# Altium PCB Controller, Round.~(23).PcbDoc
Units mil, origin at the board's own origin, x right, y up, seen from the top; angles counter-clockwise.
Board outline 1800 x 1800 mil, 4 copper layers (Top Layer, Signal 1, Signal 2, Bottom Layer); 49 components, 56 nets, 216 pads, 8 vias.
Unrouted connection lines stored in the file: 90.
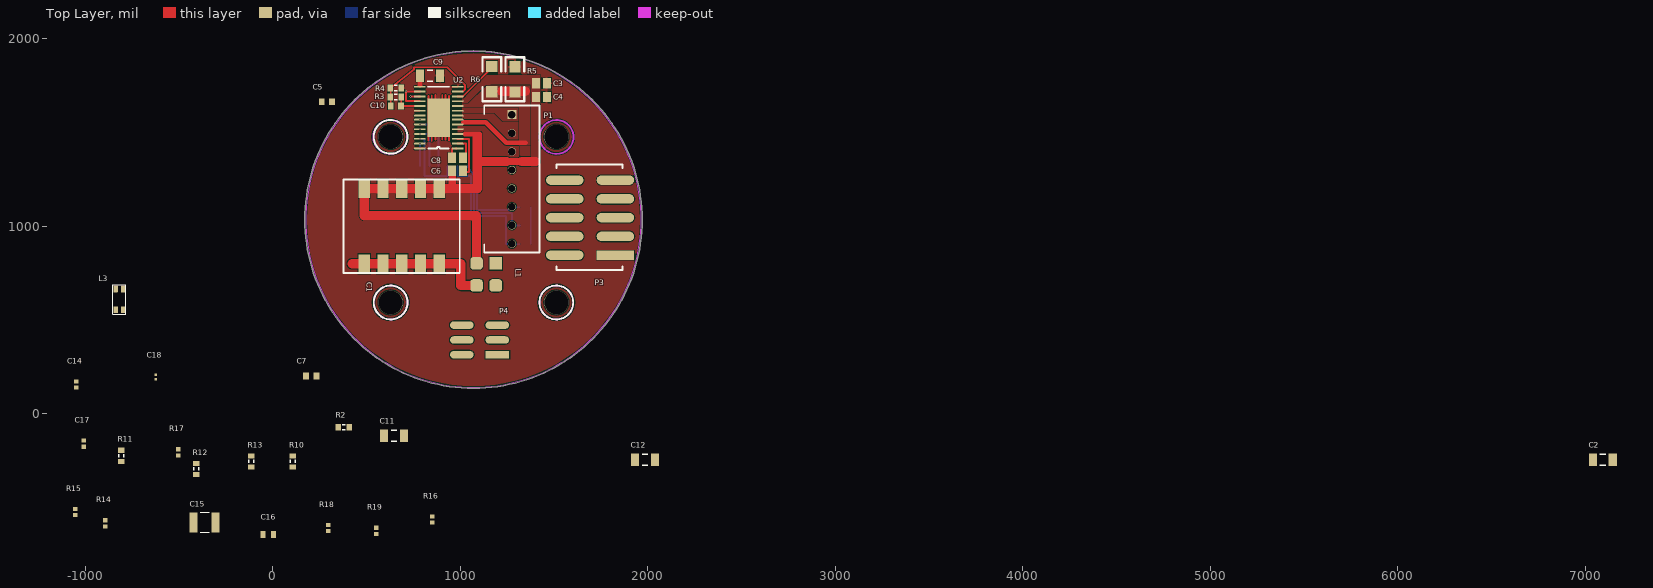
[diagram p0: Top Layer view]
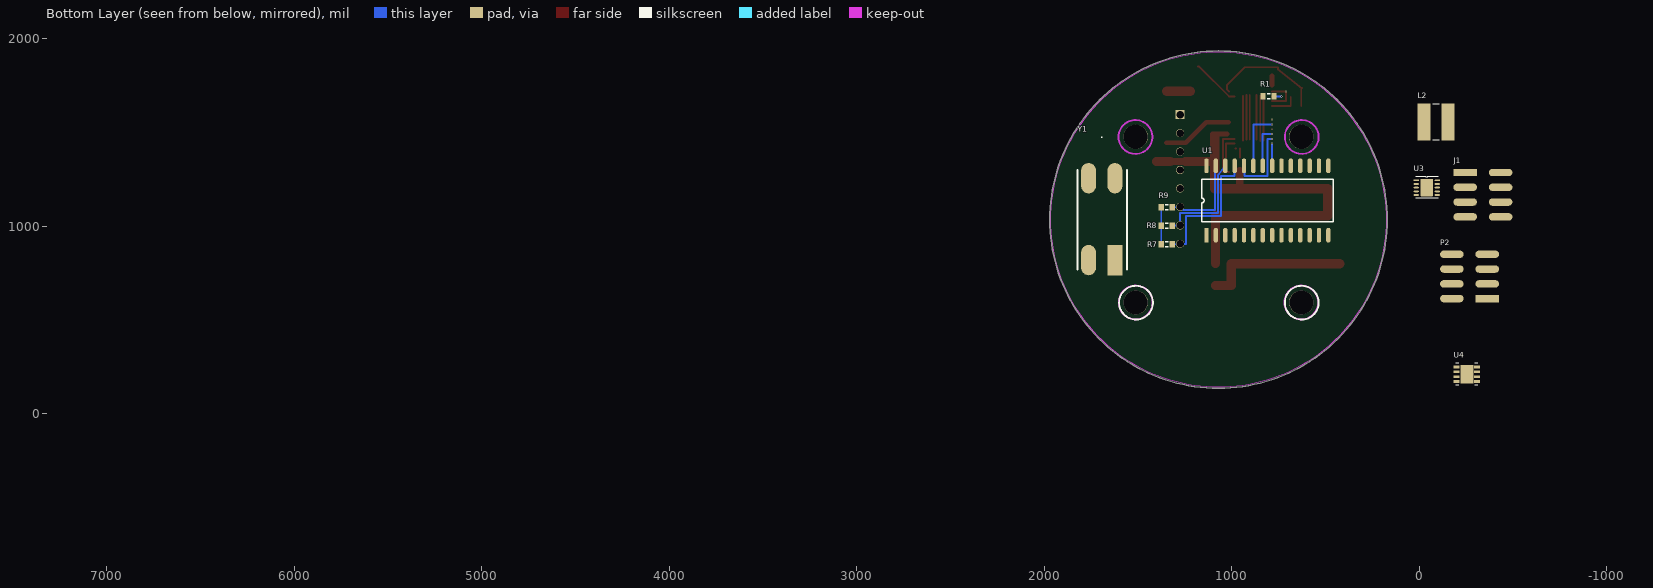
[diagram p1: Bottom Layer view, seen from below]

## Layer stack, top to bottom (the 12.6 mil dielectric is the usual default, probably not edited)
Top Layer: signal copper 1.4
Dielectric: core 12.6, FR-4, Dk 4.8
Signal 1: signal copper 1.4
Dielectric: prepreg 12.6, FR-4, Dk 4.8
Signal 2: signal copper 1.4
Dielectric: core 12.6, FR-4, Dk 4.8
Bottom Layer: signal copper 1.4

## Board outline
1070,135 cw(c1070,1035) 170,1035 cw(c1070,1035) 1070,1935 cw(c1070,1035) 1970,1035 cw(c1070,1035)

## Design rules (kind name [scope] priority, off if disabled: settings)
Clearance [All] p1: gap=5
HoleSize [All] p1: absolutevalues=TRUE maxlimit=130 minlimit=1 maxpercent=80.000 minpercent=20.000
PolygonConnect PolygonConnect_2 [WithinRoom('DontPour1') vs InNet('GND')] p1: connectstyle=NoConnect reliefconductorwidth=10 reliefentries=4 polygonreliefangle="90 Angle"
PolygonConnect PolygonConnect_1 [(InComponent('C1')) vs InNet('GND')] p2: connectstyle=NoConnect reliefconductorwidth=10 reliefentries=4 polygonreliefangle="90 Angle"
PolygonConnect [(InNet('NetP1_1') OR InNet('NetP1_2') OR InNet('NetP1_3') OR InNet('VM') OR InNet('VSENSE')) vs (InNet('NetP1_1') OR InNet('NetP1_2') OR InNet('NetP1_3') OR InNet('VM') OR InNet('VSENSE'))] p3: connectstyle=Direct reliefconductorwidth=10 reliefentries=4 polygonreliefangle="90 Angle"
RoomDefinition DontPour1 [InNet('GND') And OnLayer('TopLayer')] p1: confinementstyle=ConfineOut formatcopy=TRUE lockcomponents=FALSE outline 919.36,858.74 1037.37,858.74 1037.71,793.67 1037.71,732.35 1138.77,732.35 1138.77,624.69 920.46,624.69 920.46,640.36
RoomDefinition Controller [InComponentClass('Controller')] p2: confinementstyle=ConfineIn formatcopy=TRUE lockcomponents=FALSE outline -1190,-875 7190,-875 7190,2350 -1190,2350
RoutingVias [All] p1: holewidth=28 width=50 viastyle="Through Hole" minholewidth=6 minwidth=7.5 maxholewidth=28 maxwidth=50
SilkscreenOverComponentPads [All] p1: minsilkscreentomaskgap=10
SolderMaskExpansion [All] p1: expansion=4
Width [InNet('VM')] p1: maxlimit=100 minlimit=20 preferedwidth=40
26 further rules are at their usual default settings.

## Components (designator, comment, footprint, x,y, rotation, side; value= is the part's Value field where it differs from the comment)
C1 "Cap Pol1" CAPSTICK-CS4-5-SMD 486.68,1199.77 r0 top
C2 "Cap Semi" C1206 7095,-245 r0 top
C3 "Cap Semi" C0805 1432,1763 r180 top
C4 "Cap Semi" C0805 1432,1689 r180 top
C5 "Cap Semi" 1608[0603] 288,1664 r0 top
C6 "Cap Semi" C0805 985,1295 r180 top
C7 "Cap Semi" 1608[0603] 204,201 r0 top
C8 "Cap Semi" C0805 985,1365 r180 top
C9 "Cap Semi" C1206 838,1803 r180 top
C10 "Cap Semi" 1608[0603] 656,1641.38 r180 top
C11 "Cap Semi" C1206 646,-119 r0 top
C12 "Cap Semi" C1206 1985,-245 r0 top
C14 "C1005X7R1E103K" 0402 -1050,155 r90 top
C15 "C3225X7R2A225K230AB" 1210 -365,-580 r0 top
C16 "C1608X5R0J106M" 0603 -25,-645 r0 top
C17 "C0402C330J5GAC" 0402 -1010,-160 r90 top
C18 "GRM033R61A472KA01D" 0201 -625,195 r90 top
J1 "M80-8280842" M8082808DIL -435,1050 r0 bottom
L1 "DLW5BTM501SQ2" DLW5A_5B 1086.3,801.85 r0 top
L2 "LPS5030-823MLB" LPS5030 -90,1555 r180 bottom
L3 "SRF3216-222Y" SRF3216 -800,555 r180 top
P1 "MKS 1658-6-0-808" MKS_1658_A_KF 1275,1595 r270 top
P2 "M80-8280842" M8082808DIL -175,850 r180 bottom
P3 "N2510-6V0C-RB-WD" N2510_SMD 1826.98,845.64 r180 top
P4 "M80-8280642" M8082806DIL 1008,472 r0 top
R1 "Res3" J1-0603 803,1694 r180 bottom
R2 "Res3" J1-0603 378,-72 r0 top
R3 "Res3" J1-0603 655,1689 r0 top
R4 "Res3" J1-0603 655,1737 r180 top
R5 "Res3" 1206 1291,1851 r270 top
R6 "Res3" 1206 1168,1717 r90 top
R7 "Res3" J1-0603 1346,904 r0 bottom
R8 "Res3" J1-0603 1346,1003 r0 bottom
R9 "Res3" J1-0603 1346,1101 r0 bottom
R10 "Res3" J1-0603 105,-255 r90 top
R11 "Res3" J1-0603 -810,-225 r90 top
R12 "Res3" J1-0603 -410,-295 r90 top
R13 "Res3" J1-0603 -115,-255 r90 top
R14 "CRCW0402665KFKED" 0402 -895,-585 r90 top
R15 "CRCW040253K6FKED" 0402 -1055,-525 r90 top
R16 "CRCW040246K4FKED" 0402 850,-565 r90 top
R17 "CRCW040242K2FKED" 0402 -504.13,-206.31 r90 top
R18 "CRCW040210K0FKED" 0402 295,-610 r90 top
R19 "CRCW040280K6FKED" 0402 550,-625 r90 top
U1 "PIC_SERVO_SC" SOP28 1134,952 r90 bottom
U2 "DRV8313" HTSSOP28 985,1415 r180 top
U3 "LTC2864xDD" DD10 15,1245 r180 bottom
U4 "TPS54061DRBR" S-PVSON-N8 -255,210 r180 bottom
Y1 "MA-506 10.0000M-C0" MA506 1623,819 r0 bottom

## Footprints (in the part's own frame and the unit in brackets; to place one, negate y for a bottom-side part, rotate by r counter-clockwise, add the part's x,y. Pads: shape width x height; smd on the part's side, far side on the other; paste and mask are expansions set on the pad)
0201 [mil]
  rect 14x13 smd: 1(-11.5,0) 2(11.5,0)
0402 [mil]
  rect 22x24 smd: 1(-16.5,0) 2(16.5,0)
0603 [mil]
  rect 26x38 smd: 1(-27.5,0) 2(27.5,0)
1206 [mil]
  rect 60x60 smd: 1(0,0) 2(135,0)
  silkscreen extent -50,-50 185,50
1210 [mil]
  rect 44x106 smd: 1(-59,0) 2(59,0)
  silkscreen extent -24,-53 24,53
1608[0603] [mm] "Chip Capacitor, Body 1.6x0.8mm, IPC High Density"
  rect 0.8x0.9 smd: 1(-0.7,0) 2(0.7,0)
  body extent -0.87,-0.48 0.87,0.48, height 1.3
C0805 [mm] "Chip Capacitor, Body 2.0x1.3mm, IPC High Density"
  rect 1.1x1.4 smd: 1(-0.75,0) 2(0.75,0)
  body extent -1.1,-0.72 1.1,0.72, height 1.4
C1206 [mm] "Chip Capacitor, Body 3.2x1.6mm, IPC High Density"
  rect 1.1x1.7 smd: 1(-1.35,0) 2(1.35,0)
  silkscreen extent -0.4,-0.75 0.4,0.75, body extent -1.7,-0.9 1.7,0.9, height 1.3
CAPSTICK-CS4-5-SMD [mil]
  rect 60x100 smd: 1(0,0) 1(100,0) 1(200,0) 1(300,0) 1(400,0) 2(0,-400) 2(100,-400) 2(200,-400) 2(300,-400) 2(400,-400)
  silkscreen extent -110,-450 510,50
DD10 [mm]
  rect 0.7x0.25 smd: 1(0,0)
  oval 0.7x0.25 smd: 2(0,-0.5) 3(0,-1) 4(0,-1.5) 5(0,-2) 6(2.85,-2) 7(2.85,-1.5) 8(2.85,-1) 9(2.85,-0.5) 10(2.85,0)
  rrect10% 1.65x2.38 smd: Pad(1.425,-1)
  silkscreen extent -0.1,-2.45 2.95,0.5
DLW5A_5B [mm]
  rect 1.7x1.7 smd: 1(2.6,0)
  rrect50% 1.7x1.7 smd: 2(0,0) 3(0,-3) 4(2.6,-3)
HTSSOP28 [mm] "HTTSSOP 28 Pin Package, TI"
  rect 1.55x0.25 smd: 1(0,0)
  rrect50% 1.55x0.25 smd: 2(0,-0.65) 3(0,-1.3) 4(0,-1.95) 5(0,-2.6) 6(0,-3.25) 7(0,-3.9) 8(0,-4.45) 9(0,-5.1) 10(0,-5.75) 11(0,-6.4) 12(0,-7.05) 13(0,-7.7) 14(0,-8.35) 15(5.1,-8.35) 16(5.1,-7.7) 17(5.1,-7.05) 18(5.1,-6.4) 19(5.1,-5.75) 20(5.1,-5.1) 21(5.1,-4.45) 22(5.1,-3.9) 23(5.1,-3.25) 24(5.1,-2.6) 25(5.1,-1.95) 26(5.1,-1.3) 27(5.1,-0.65) 28(5.1,0)
  rect 3.1x5.18 smd: Pad(2.55,-4.15)
  silkscreen extent 1.15,-8.35 4,0
J1-0603 [mm] "Chip Resistor, Body 1.6x0.8mm, IPC High Density"
  rect 0.7x0.9 smd: 1(-0.75,0) 2(0.75,0)
  silkscreen extent -0.2,-0.35 0.2,0.35, body extent -0.85,-0.48 0.85,0.48, height 0.9
LPS5030 [mil]
  rect 68.5x197 smd: 1(-64.25,0) 2(64.25,0)
  silkscreen extent -17,-96 17,96
M8082806DIL [mm] "Harwin 2x3"
  rect 3.2x1 smd: 1(4.8,-4)
  oval 3.2x1 smd: 2(0,-4) 3(4.8,-2) 4(0,-2) 5(4.8,0) 6(0,0)
M8082808DIL [mm] "Harwin M80-82808 SMT DIL Male Connector"
  rect 3.2x1 smd: 1(4.8,-6)
  oval 3.2x1 smd: 2(0,-6) 3(4.8,-4) 4(0,-4) 5(4.8,-2) 6(0,-2) 7(4.8,0) 8(0,0)
MA506 [mm]
  rect 2.05x4.1 smd: 1(0,0)
  oval 2.05x4.1 smd: 2(0,-11.1) 3(3.55,-11.1) 4(3.55,0)
  round 0.9 on Bottom Overlay: ""(-0.2,3.15)
  silkscreen extent -1.65,-16.65 5.05,1.26
MKS_1658_A_KF [mm] "Stocko MKS-1658 Shrouded Header Connector"
  rect 1.2x1.2 hole 1: 1(0,0)
  round 1.1 hole 1: 2(2.5,0) 3(5,0) 4(7.5,0) 5(10,0) 6(12.5,0) 7(15,0) 8(17.5,0)
  silkscreen extent -1.25,-3.75 18.7,3.75
N2510_SMD [mil]
  rect 200x50 smd: 1(0,0)
  oval 200x50 smd: 2(270.08,0) 3(0,-100) 4(270.08,-100) 5(0,-200) 6(270.08,-200) 7(0,-300) 8(270.08,-300) 9(0,-400) 10(270.08,-400)
  silkscreen extent -37,-484 315,79
S-PVSON-N8 [mm]
  rect 0.805x0.37 smd: 1(-1.402,0.975) 2(-1.402,0.325) 3(-1.402,-0.325) 4(-1.402,-0.975) 5(1.402,-0.975) 6(1.402,-0.325) 7(1.402,0.325) 8(1.402,0.975)
  rect 1.75x2.5 smd paste-1.237: 9(0,0)
  silkscreen extent -1.5,-1.5 1.5,1.5
SOP28 [mm]
  rect 2x0.6 smd: 1(0,0)
  oval 2x0.6 smd: 2(0,-1.27) 3(0,-2.54) 4(0,-3.81) 5(0,-5.08) 6(0,-6.35) 7(0,-7.62) 8(0,-8.89) 9(0,-10.16) 10(0,-11.43) 11(0,-12.7) 12(0,-13.97) 13(0,-15.24) 14(0,-16.51) 15(9.4,-16.51) 16(9.4,-15.24) 17(9.4,-13.97) 18(9.4,-12.7) 19(9.4,-11.43) 20(9.4,-10.16) 21(9.4,-8.89) 22(9.4,-7.62) 23(9.4,-6.35) 24(9.4,-5.08) 25(9.4,-3.81) 26(9.4,-2.54) 27(9.4,-1.27) 28(9.4,0)
  silkscreen extent 1.83,-17.14 7.56,0.63
SRF3216 [mm]
  rect 0.6x0.9 smd: 1(0,0)
  rrect10% 0.6x0.9 smd: 2(0,-2.8) 3(1,-2.8) 4(1,0)
  silkscreen extent -0.4,-3.4 1.4,0.6

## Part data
C1: "Polarized Capacitor (Radial)"
C2 C3 C4 C5 C6 C7 C8 C9 C10 C11 C12: "Capacitor (Semiconductor SIM Model)"
C15: "C3225X7R2A225K23"
C18: "GRM033R61A472KA0"
J1 P2: library part "Header 8", "Header, 8-Pin"
L1 L3: library part "COMMON MODE CHOKE"
P1: library part "Header 8"
P3: library part "Header 5X2", "Header, 5-Pin, Dual row"
P4: library part "Header 6", "Header, 6-Pin"
R1 R2 R3 R4 R5 R6 R7 R8 R9 R10 R11 R12 R13: "Resistor"
U4: "Imported"
Y1: library part MA-406/MA-505/MA-506

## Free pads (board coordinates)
  round 128.5 hole 128.5: ""(628,593) ""(628,1477) ""(1512,593) ""(1512,1477)

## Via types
v1: diameter 10, hole 6, Top Layer to Bottom Layer, 8 vias

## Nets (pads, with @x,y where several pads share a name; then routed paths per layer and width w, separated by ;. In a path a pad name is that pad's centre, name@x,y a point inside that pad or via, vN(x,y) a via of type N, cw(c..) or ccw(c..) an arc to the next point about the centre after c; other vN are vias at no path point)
\ENC_A: P3.5
\ENC_B: P3.7
\ENC_INDEX: P3.9
\FAULT: R11.2 U1.3 U2.16 U2.18 | length 199.6
  Top Layer w10: U2.18 710,1666.97 v1(710,1718.15) U2.16
ADDR_IN: U1.28
ADDR_OUT: U1.13
CUR_SENSE: C10.1 R3.2 U1.2 U2.19 | length 147.3
  Top Layer w10: R3.2 684.53,1641.38 U2.19
ENC_A: P3.6 U1.5
ENC_B: P3.8 U1.6
ENC_INDEX: P3.10 R2.1
GND: C1.2 C3.1 C4.1 C9.1 L1.3 R4.1 R5.1 R10.1 U2.14 U2.20 U2.28 U2.Pad | length 2214.3
  Top Layer w10: 829.58,1457.03 829.58,1695.26 ; 847.36,1454.88 847.36,1698.94 ; 866.37,1461.32 866.37,1699.56 ; 903.47,1462.85 903.47,1701.09 ; 920.64,1462.54 920.64,1700.78 ; 939.96,1457.03 939.96,1695.26
  Top Layer w50: 423.31,799.77 486.68,799.77 586.68,799.77 686.68,799.77 786.68,799.77 886.68,799.77 1001.81,799.77 1001.81,683.74 L1.3
HALL1: P1.8 R7.1 U1.25 | length 753.6
  Bottom Layer w10: U1.25 984,1267 1057,1267 1057,1055 1243.35,1055 1243.35,905 P1.8@1275,905 ; P1.8 P1.8@1275,905 ; R7.1@1316.47,906.02 R7.1 1275,904 P1.8@1275,905
HALL2: P1.7 R8.1 U1.26 | length 576.6
  Bottom Layer w10: U1.26 1072,1272.71 1072,1070 1275,1070 P1.7 1276.45,1003 R8.1@1317.47,1003
HALL3: P1.6 R9.1 U1.27 | length 469.3
  Bottom Layer w10: U1.27 1089.01,1317.07 1089.01,1087 1259.11,1086.99 P1.6 ; P1.6@1276.87,1101 R9.1
LIMIT1: P4.2 R13.2 U1.16
LIMIT2: P4.5 R12.2 U1.14
NetC5_2: C5.2 U1.9 Y1.1
NetC6_1: C6.1 U2.3 | length 269
  Top Layer w10: U2.3 1046.18,1466.18 1046.18,1290 C6.1@1014.53,1290
NetC7_2: C7.2 U1.10 Y1.4
NetC8_1: C8.1 U2.2 | length 120.6
  Top Layer w10: U2.2 1030,1440.59 C8.1@1030,1365
NetC8_2: C8.2 U2.1 | length 55.5
  Top Layer w10: C8.2@955,1365 U2.1@955,1415 ; U2.1@975,1415 U2.1@980.47,1415
NetC9_2: C9.2 U2.15 | length 49.4
  Top Layer w25: 784.85,1753.57 C9.2
NetC10_2: C10.2 R3.1 R4.2 U2.13 | length 619.5
  Top Layer w10: R4.2 753.2,1837.2 753,1848 928.87,1848 1025.51,1751.36 1025.51,1730.3 U2.13@1013.36,1718.15 ; C10.2 R4.2@628.44,1737
NetC14_1: C14.1 L2.2 U4.8
NetC14_2: C14.2 U4.1
NetC15_1: C15.1 L3.2 R14.1 U4.2
NetC17_1: C17.1 R16.2 U4.6
NetC18_1: C18.1 R16.1
NetJ1_1: J1.1 L1.4 L3.4 P2.1
NetJ1_2: J1.2 L1.1 L3.1 P2.2
NetP1_1: P1.1 U2.9
NetP1_2: P1.2 U2.8
NetP1_3: P1.3 U2.5
NetR1_2: R1.2 U2.17 | length 92.7
  Top Layer w10: v1(733,1692.56) U2.17
  Bottom Layer w10: v1(733,1692.56) R1.2@774.47,1692.56
NetR2_2: R2.2 U1.15
NetR6_2: R6.2 U2.12 | length 261.6
  Top Layer w10: U2.12 1013.98,1692.56 1172.42,1851 R6.2@1181,1851
NetR14_2: R14.2 R17.1 U4.3
NetR15_2: R15.2 R18.1 U4.5
NetR19_1: R19.1 U4.4
NetU1_4: U1.4 U2.24
  other v1: 784.21,1517.36
NetU1_11: U1.11 U2.22
  other v1: 784.04,1568.44
NetU1_12: U1.12 U3.3
NetU1_17: U1.17 U3.4
NetU1_18: U1.18 U3.1
NetU1_21: U1.21 U2.27 | length 118.5
  Bottom Layer w10: U1.21@784.21,1322.08 v1(784.21,1440.59)
NetU1_22: U1.22 U2.25 | length 220.5
  Bottom Layer w10: v1(784.21,1491.77) 835,1491.77 U1.22@835,1322.08
NetU1_23: U1.23 U2.23 | length 320.7
  Bottom Layer w10: v1(784.21,1542.95) 884,1542.95 U1.23
NetU1_24: U1.24 U2.26 | length 401
  Bottom Layer w10: v1(784.21,1466.18) 808,1466.18 808,1267 931,1267 U1.24@931,1322.08
RS422_RX_A: J1.3 P2.3 U3.9
RS422_RX_B: J1.4 P2.4 U3.8
RS422_TX_A: J1.5 P2.5 U3.7
RS422_TX_B: J1.6 P2.6 U3.6
SGND: C2.2 C5.1 C7.1 C11.1 C12.2 C15.2 C16.2 C17.2 C18.2 L3.3 P1.5 P3.3 P4.4 P4.6 R10.2 R17.2 R18.2 R19.2 U1.8 U1.19 U3.5 U3.Pad U4.7
VCC: C2.1 C11.2 C12.1 C16.1 L2.1 P1.4 P3.2 P4.1 P4.3 R1.1 R7.2 R8.2 R9.2 R11.1 R12.1 R13.1 R15.1 U1.1 U1.7 U1.20 U3.10 | length 197
  Bottom Layer w10: R7.2 R8.2 R9.2
VM: C1.1 C3.2 C4.2 C6.2 L1.2 U2.4 U2.11 | length 2359.2
  Top Layer w25: 1024,1491.77 1103,1491.77
  Top Layer w35: 1246,1345 1326.65,1345
  Top Layer w40: 955.47,1200 C6.2
  Top Layer w50: L1.2 1086.3,1056.68 486.68,1056.68 486.68,1199.77 586.68,1199.77 686.68,1199.77 786.68,1199.77 886.68,1199.77 1090.39,1199.77 1090.39,1478.74 ; 1096,1345 1246,1345 ; 1326.65,1345 1401,1345
VSENSE: R5.2 R6.1 U2.6 U2.7 U2.10 | length 502.8
  Top Layer w25: 1016.76,1555 1135,1555 1245,1445 1347,1445
  Top Layer w50: 1220,1720 1347,1720
pads on no net: J1.7 J1.8 P2.7 P2.8 P3.1 P3.4 U2.21 U3.2 U4.9 Y1. Y1.2 Y1.3

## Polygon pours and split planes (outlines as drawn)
VM on Top Layer "Top Layer-No Net" (solid, pour order 94): 1377.15,1650.24 1427,1650.24 1424.56,1650.24 1424.56,1314.74 1424.56,1315.12 1377.15,1315.12
GND on Top Layer "Top Layer-No Net" (solid, pour order 91): 1070,140 cw(c1070,1035) 175,1035 cw(c1070,1035) 1070,1930 cw(c1070,1035) 1965,1035 cw(c1070,1035)
NetP1_2 on Top Layer "Top Layer-No Net" (solid, pour order 64): 1009,1605 1309.78,1605 1309.78,1450 1243,1450 1241,1452.14 1129,1571.86 1021,1571 1009,1571
VSENSE on Top Layer "Top Layer-No Net" (solid, pour order 78): 1315.41,1627 1371.74,1627 1371.74,1433 1366,1433 1315,1433
VM on Top Layer "Top Layer-No Net" (solid, pour order 76): 1009,1652 1427,1650 1427,1806 1080,1806 1045,1771 1045,1709 1018.56,1680 1009,1680
VSENSE on Top Layer "Top Layer-No Net" (solid, pour order 72): 1009,1627 1383,1627 1384,1750 1140,1750 1042,1652 1009,1652
NetP1_1 on Top Layer "Top Layer-No Net" (solid, pour order 60): 1009,1630 1310,1630 1310,1560 1225,1560 1180,1605 1009,1605
NetP1_3 on Top Layer "Top Layer-No Net" (solid, pour order 66): 986,1536 988,1534 1155,1534 1163,1534 1259,1438 1261,1436 1311,1436 1311,1362 1305,1356 1304,1357 1109,1357 1109,1484 1099,1494 1093,1500 986,1500

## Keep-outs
Keep-Out Layer:
  circle w10: c628,593 r90.15
  circle w10: c1512,593 r90.15
  circle w10: c1513,1476 r90.15
  circle w10: c626,1476 r90.15
  circle w5: c1070,1035 r895

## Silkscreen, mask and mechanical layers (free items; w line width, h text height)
Top Overlay:
  circle w10: c628,593 r90.15
  circle w10: c628,1477 r90.15
  circle w10: c1512,593 r90.15
Bottom Overlay:
  circle w10: c626,592 r90.15
  circle w10: c1510,592 r90.15
Mechanical 1:
  circle w5: c1512,1477 r64.25
  circle w5: c1512,593 r64.25
  circle w5: c628,593 r64.25
  circle w5: c628,1477 r64.25
  circle w5: c1070,1035 r900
